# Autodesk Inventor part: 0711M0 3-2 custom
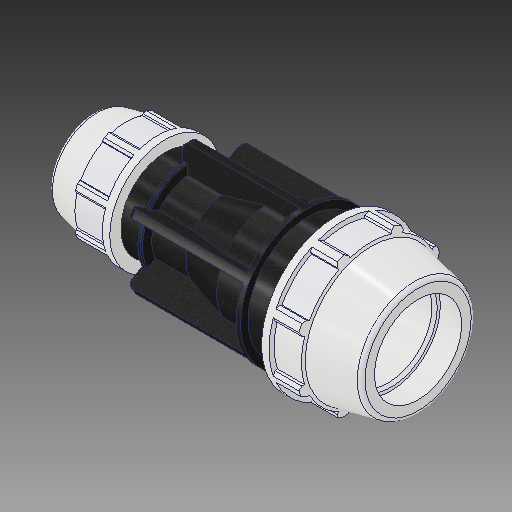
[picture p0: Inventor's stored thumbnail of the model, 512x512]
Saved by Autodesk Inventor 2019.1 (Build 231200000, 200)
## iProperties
Created: 2017-02
Part Number: 0711M0 3-2 custom
Material: PVC-Piping
Description: PLASSON REDUCING COUPLER 3'' - 2''
Document SubType Name: Modeling
Designer: KIM
Mass: 92.6774 g
Surface Area: 199.44 cm^2
Volume: 66.1981 cm^3
Density: 1.4 g/cm^3
Appearance: PTFE
Author: KIM
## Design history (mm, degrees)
derived "0711M0.ipt"
feature "Solid1::0711M0.ipt"
tag "TaggingFeature1"
body "Solid1"
other parameters: "d2" = 88.7, "d4" = 27.5, "d5" = 47.14286, "d7" = 151.892, "d9" = 47.14286, "d11" = 4.71429, "d12" = 121.5136, "d13" = 120 deg, "d14" = 115.31, "d15" = 12 deg, "d16" = 136.7028, "d18" = 4.435, "d19" = 35 deg, "d20" = 17.5 deg, "d21" = 141.25956, "d23" = 0, "d25" = 360 deg, "d27" = 3.03784, "d42" = 36.3, "d46" = 2.661, "d52" = 113.7931, "d53" = 12 deg, "d54" = 151.892, "d56" = 90.15, "d57" = 60.1, "d58" = 79.83, "d59" = 54.09, "d60" = 101.727, "d61" = 90.424, "d62" = 33, "d63" = 39.6, "d64" = 120 deg, "d65" = 113.03, "d68" = 23.57143, "d74" = 105.1179, "d75" = 35 deg, "d76" = 17.5 deg, "d78" = 0, "d80" = 360 deg, "d85" = 2.2606, "d88" = 1.202, "d93" = 134, "d94" = 106.3244, "d97" = 3.41407, "d98" = 7.53533, "d99" = 0, "d100" = 6.07568, "d102" = 360 deg, "d104" = 2, "d106" = 0, "d107" = 7.53533, "d108" = 0, "d109" = 7.53533, "d110" = 0, "d_" = 88.7, "E_" = 151.892, "l_" = 151.892, "d_1" = 60.1, "E_1" = 113.03, "l_1" = 134, "d96" = 10.2422
